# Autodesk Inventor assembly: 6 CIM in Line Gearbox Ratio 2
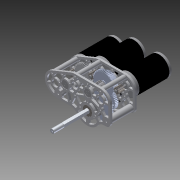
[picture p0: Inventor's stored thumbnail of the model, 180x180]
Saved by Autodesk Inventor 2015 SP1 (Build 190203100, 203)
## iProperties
Created: 2014-11
Part Number: 6 CIM in Line Gearbox Ratio 2
Document SubType Name: Assembly
Designer: Michael
Mass: 4438.01 g
Surface Area: 2514.13 cm^2
Volume: 1336.24 cm^3
Density: 3.32126 g/cm^3
Author: Michael
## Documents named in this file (30)
- C:\Users\User\Documents\6 CIM Gearbox Pack and Go\6 CIM in Line Gearbox Ratio 2.iam
- C:\Users\User\Documents\6 CIM Gearbox Pack and Go\Gearbox Plate Ratio 2.ipt
- C:\Users\User\Documents\6 CIM Gearbox Pack and Go\40T .5 inch.ipt
- C:\Users\User\Documents\6 CIM Gearbox Pack and Go\11t.ipt
- C:\Users\User\Documents\6 CIM Gearbox Pack and Go\50t.ipt
- C:\Users\User\Documents\6 CIM Gearbox Pack and Go\36t.ipt
- C:\Users\User\Documents\6 CIM Gearbox Pack and Go\217-2000 CIM motor.ipt
- C:\Users\User\Documents\6 CIM Gearbox Pack and Go\User Library-16T Gear AndyMark am-0747.ipt
- C:\Users\User\Documents\6 CIM Gearbox Pack and Go\40tDogGear.ipt
- C:\Users\User\Documents\6 CIM Gearbox Pack and Go\60tDogGear.ipt
- C:\Users\User\Documents\6 CIM Gearbox Pack and Go\Gearbox Plate Ratio 2 MIR.ipt
- C:\Users\User\Documents\6 CIM Gearbox Pack and Go\Standoff.ipt
- C:\Users\User\Documents\6 CIM Gearbox Pack and Go\Big Standoff.ipt
- C:\Users\User\Documents\6 CIM Gearbox Pack and Go\217-2428-027 Rev1_97414A630.ipt
- C:\Users\User\Documents\6 CIM Gearbox Pack and Go\217-3423-005 Rev1.ipt
- C:\Users\User\Documents\6 CIM Gearbox Pack and Go\217-3195-200 Rev1.iam
- C:\Users\User\Documents\6 CIM Gearbox Pack and Go\217-3489.ipt
- C:\Users\User\Documents\6 CIM Gearbox Pack and Go\217-3423-006 Rev1.ipt
- C:\Users\User\Documents\6 CIM Gearbox Pack and Go\217-3423-008 Rev1.ipt
- C:\Users\User\Documents\6 CIM Gearbox Pack and Go\217-2778-001 Rev2_NCQ8A075-050M.iam
- C:\Users\User\Documents\6 CIM Gearbox Pack and Go\217-3421-007 Rev1.ipt
- C:\Users\User\Documents\6 CIM Gearbox Pack and Go\217-3423-009 Rev1.ipt
- C:\Users\User\Documents\6 CIM Gearbox Pack and Go\217-3423-003 Rev1.ipt
- C:\Users\User\Documents\6 CIM Gearbox Pack and Go\217-2731.ipt
- C:\Users\User\Documents\6 CIM Gearbox Pack and Go\217-3423-004 Rev1.ipt
- C:\Users\User\Documents\6 CIM Gearbox Pack and Go\217-2743.ipt
- C:\Users\User\Documents\6 CIM Gearbox Pack and Go\217-2734.ipt
- C:\Users\User\Documents\6 CIM Gearbox Pack and Go\217-2733.ipt
- C:\Users\User\Documents\6 CIM Gearbox Pack and Go\217-2640-STEP-20140807.ipt
- C:\Users\User\Documents\6 CIM Gearbox Pack and Go\6cim shaft.ipt
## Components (44 placed, 29 different names)
1. Gearbox Plate Ratio 2:1 — Mate:1, Mate:2, Mate:5, Mate:7, Mate:8, Mate:12, Mate:13, Mate:14, Mate:15, Mate:16, Mate:17, Mate:18, Mate:19, Mate:20, Mate:25, Mate:26, Angle:3, Mate:30, Mate:31, Mate:32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
2. 40T .5 inch:1 — Mate:2, Mate:10, Rotation:5, Rotation:6
3. 11t:1 — Mate:1, Mate:10, Flush:1, Rotation:5
4. 11t:2 — Mate:5, Flush:1, Flush:2, Rotation:6, Rotation:7, Flush:3
5. 50t:1 — Mate:7, Rotation:4, Mate:11, Angle:1, Mate:22, Rotation:7, Mate:24, Angle:2, Flush:3
6. 11t:3 — Mate:8, Rotation:4, Flush:2
7. 36t:1 — Mate:11, Angle:1, Mate:22, Rotation:8, Flush:4
8. 217-2000 CIM motor:1 — Mate:13, Mate:15, Mate:18
9. 217-2000 CIM motor:2 — Mate:14, Mate:16, Mate:19
10. 217-2000 CIM motor:3 — Mate:12, Mate:17, Mate:20
11. User Library-16T Gear AndyMark am-0747:1 — Mate:24, Angle:2, Rotation:9, Mate:81
12. 40tDogGear:1 — Mate:25, Rotation:8, Mate:71, Mate:72
13. 60tDogGear:1 — Mate:26, Angle:3, Rotation:9, Mate:76, Mate:77, Mate:81
14. Gearbox Plate Ratio 2 MIR:1 — Mate:30, Mate:31, Mate:32, Mate:36, Mate:37, Mate:38, Mate:66, Mate:79, Mate:80, Mate:82, Mate:83, Mate:87, Mate:88
15. Standoff:1 — Mate:35, Mate:36
16. Big Standoff:1 — Mate:33, Mate:34
17. Standoff:2 — Mate:41, Mate:42
18. Standoff:3 — Mate:39, Mate:40
19. Big Standoff:2 — Mate:37, Mate:38
20. 217-2428-027 Rev1_97414A630:1 — Mate:52, Mate:53
21. 217-3423-005 Rev1:1 — Mate:44, Mate:45, Mate:46, Mate:47, Mate:48, Mate:56, Mate:57, Mate:58
22. 217-3195-200 Rev1:1 [sub-assembly] — Mate:54, Mate:59, Mate:61
23. 217-3489:1 — Mate:50, Mate:51, Mate:54
24. 217-3423-006 Rev1:1 — Mate:55, Mate:58, Mate:63
25. 217-3423-006 Rev1:2 — Mate:43, Mate:46, Mate:60
26. 217-3423-008 Rev1:1 — Mate:49, Mate:50, Mate:51, Mate:52, Mate:53, Mate:59, Mate:64, Mate:65, Mate:68
27. 217-2778-001 Rev2_NCQ8A075-050M:1 [sub-assembly] — Mate:47, Mate:48, Mate:49, Mate:61
28. 217-3421-007 Rev1:1 — Mate:43, Mate:44, Mate:45
29. 217-3421-007 Rev1:2 — Mate:55, Mate:56, Mate:57, Mate:62
30. 217-3423-009 Rev1:1 — Mate:64, Mate:65
31. 217-3423-003 Rev1:1 — Mate:66, Mate:69, Mate:78
32. 217-2731:1 — Mate:67, Mate:68, Mate:70
33. 217-3423-004 Rev1:1 — Mate:69, Mate:70, Mate:75
34. 217-2743:1 — Mate:71, Mate:72, Mate:75, Flush:4
35. 217-2734:1 — Mate:76, Mate:77, Mate:78, Mate:92, Mate:93
36. 217-2734:2 — Mate:79, Mate:80
37. 217-2733:1 — Mate:82, Mate:87, Mate:95, Flush:6
38. 217-2733:2 — Mate:83, Mate:88, Mate:94, Flush:5
39. 217-2733:3 — Mate:85, Mate:86
40. 217-2733:4 — Mate:84, Mate:89
41. 217-2640-STEP-20140807:1 — Mate:90, Mate:91
42. 217-2640-STEP-20140807:2 — Mate:90, Mate:91, Mate:92, Mate:93
43. 6cim shaft:1 — Mate:94, Flush:5
44. 6cim shaft:3 — Mate:95, Flush:6
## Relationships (99: Mate 84, RelateRotation 6, Flush 6, Angle 3)
- Mate:1: Gearbox Plate Ratio 2:1 ↔ 11t:1
- Mate:2: Gearbox Plate Ratio 2:1 ↔ 40T .5 inch:1
- Mate:5: Gearbox Plate Ratio 2:1 ↔ 11t:2
- Mate:7: Gearbox Plate Ratio 2:1 ↔ 50t:1
- Mate:8: Gearbox Plate Ratio 2:1 ↔ 11t:3
- Mate:10: 40T .5 inch:1 ↔ 11t:1
- Rotation:4 [RelateRotation]: 50t:1 ↔ 11t:3
- Mate:11: 50t:1 ↔ 36t:1
- Angle:1: 50t:1 ↔ 36t:1
- Mate:12: Gearbox Plate Ratio 2:1 ↔ 217-2000 CIM motor:3
- Mate:13: Gearbox Plate Ratio 2:1 ↔ 217-2000 CIM motor:1
- Mate:14: Gearbox Plate Ratio 2:1 ↔ 217-2000 CIM motor:2
- Mate:15: Gearbox Plate Ratio 2:1 ↔ 217-2000 CIM motor:1
- Mate:16: Gearbox Plate Ratio 2:1 ↔ 217-2000 CIM motor:2
- Mate:17: Gearbox Plate Ratio 2:1 ↔ 217-2000 CIM motor:3
- Mate:18: Gearbox Plate Ratio 2:1 ↔ 217-2000 CIM motor:1
- Mate:19: Gearbox Plate Ratio 2:1 ↔ 217-2000 CIM motor:2
- Mate:20: Gearbox Plate Ratio 2:1 ↔ 217-2000 CIM motor:3
- Flush:1: 11t:1 ↔ 11t:2
- Flush:2: 11t:2 ↔ 11t:3
- Mate:22: 50t:1 ↔ 36t:1
- Rotation:5 [RelateRotation]: 40T .5 inch:1 ↔ 11t:1
- Rotation:6 [RelateRotation]: 40T .5 inch:1 ↔ 11t:2
- Rotation:7 [RelateRotation]: 11t:2 ↔ 50t:1
- Mate:24: 50t:1 ↔ User Library-16T Gear AndyMark am-0747:1
- Angle:2: 50t:1 ↔ User Library-16T Gear AndyMark am-0747:1
- Mate:25: Gearbox Plate Ratio 2:1 ↔ 40tDogGear:1
- Mate:26: Gearbox Plate Ratio 2:1 ↔ 60tDogGear:1
- Angle:3: Gearbox Plate Ratio 2:1 ↔ 60tDogGear:1
- Rotation:8 [RelateRotation]: 36t:1 ↔ 40tDogGear:1
- Rotation:9 [RelateRotation]: User Library-16T Gear AndyMark am-0747:1 ↔ 60tDogGear:1
- Mate:30: Gearbox Plate Ratio 2:1 ↔ Gearbox Plate Ratio 2 MIR:1
- Mate:31: Gearbox Plate Ratio 2:1 ↔ Gearbox Plate Ratio 2 MIR:1
- Mate:32: Gearbox Plate Ratio 2:1 ↔ Gearbox Plate Ratio 2 MIR:1
- Mate:33: Gearbox Plate Ratio 2:1 ↔ Big Standoff:1
- Mate:34: Gearbox Plate Ratio 2:1 ↔ Big Standoff:1
- Mate:35: Gearbox Plate Ratio 2:1 ↔ Standoff:1
- Mate:36: Gearbox Plate Ratio 2 MIR:1 ↔ Standoff:1
- Mate:37: Gearbox Plate Ratio 2 MIR:1 ↔ Big Standoff:2
- Mate:38: Gearbox Plate Ratio 2 MIR:1 ↔ Big Standoff:2
- Mate:39: Gearbox Plate Ratio 2:1 ↔ Standoff:3
- Mate:40: Gearbox Plate Ratio 2:1 ↔ Standoff:3
- Mate:41: Gearbox Plate Ratio 2:1 ↔ Standoff:2
- Mate:42: Gearbox Plate Ratio 2:1 ↔ Standoff:2
- Mate:43: 217-3423-006 Rev1:2 ↔ 217-3421-007 Rev1:1
- Mate:44: 217-3423-005 Rev1:1 ↔ 217-3421-007 Rev1:1
- Mate:45: 217-3423-005 Rev1:1 ↔ 217-3421-007 Rev1:1
- Mate:46: 217-3423-005 Rev1:1 ↔ 217-3423-006 Rev1:2
- Mate:47: 217-3423-005 Rev1:1 ↔ 217-2778-001 Rev2_NCQ8A075-050M:1
- Mate:48: 217-3423-005 Rev1:1 ↔ 217-2778-001 Rev2_NCQ8A075-050M:1
- Mate:49: 217-3423-008 Rev1:1 ↔ 217-2778-001 Rev2_NCQ8A075-050M:1
- Mate:50: 217-3489:1 ↔ 217-3423-008 Rev1:1
- Mate:51: 217-3489:1 ↔ 217-3423-008 Rev1:1
- Mate:52: 217-2428-027 Rev1_97414A630:1 ↔ 217-3423-008 Rev1:1
- Mate:53: 217-2428-027 Rev1_97414A630:1 ↔ 217-3423-008 Rev1:1
- Mate:54: 217-3195-200 Rev1:1 ↔ 217-3489:1
- Mate:55: 217-3423-006 Rev1:1 ↔ 217-3421-007 Rev1:2
- Mate:56: 217-3423-005 Rev1:1 ↔ 217-3421-007 Rev1:2
- Mate:57: 217-3423-005 Rev1:1 ↔ 217-3421-007 Rev1:2
- Mate:58: 217-3423-005 Rev1:1 ↔ 217-3423-006 Rev1:1
- Mate:59: 217-3195-200 Rev1:1 ↔ 217-3423-008 Rev1:1
- Mate:60: Gearbox Plate Ratio 2:1 ↔ 217-3423-006 Rev1:2
- Mate:61: 217-3195-200 Rev1:1 ↔ 217-2778-001 Rev2_NCQ8A075-050M:1
- Mate:62: Gearbox Plate Ratio 2:1 ↔ 217-3421-007 Rev1:2
- Mate:63: Gearbox Plate Ratio 2:1 ↔ 217-3423-006 Rev1:1
- Mate:64: 217-3423-008 Rev1:1 ↔ 217-3423-009 Rev1:1
- Mate:65: 217-3423-008 Rev1:1 ↔ 217-3423-009 Rev1:1
- Mate:66: Gearbox Plate Ratio 2 MIR:1 ↔ 217-3423-003 Rev1:1
- Mate:67: Gearbox Plate Ratio 2:1 ↔ 217-2731:1
- Mate:68: 217-3423-008 Rev1:1 ↔ 217-2731:1
- Mate:69: 217-3423-003 Rev1:1 ↔ 217-3423-004 Rev1:1
- Mate:70: 217-2731:1 ↔ 217-3423-004 Rev1:1
- Mate:71: 40tDogGear:1 ↔ 217-2743:1
- Mate:72: 40tDogGear:1 ↔ 217-2743:1
- Mate:75: 217-3423-004 Rev1:1 ↔ 217-2743:1
- Mate:76: 60tDogGear:1 ↔ 217-2734:1
- Mate:77: 60tDogGear:1 ↔ 217-2734:1
- Mate:78: 217-3423-003 Rev1:1 ↔ 217-2734:1
- Mate:79: Gearbox Plate Ratio 2 MIR:1 ↔ 217-2734:2
- Mate:80: Gearbox Plate Ratio 2 MIR:1 ↔ 217-2734:2
- Mate:81: User Library-16T Gear AndyMark am-0747:1 ↔ 60tDogGear:1
- Mate:82: Gearbox Plate Ratio 2 MIR:1 ↔ 217-2733:1
- Mate:83: Gearbox Plate Ratio 2 MIR:1 ↔ 217-2733:2
- Mate:84: Gearbox Plate Ratio 2:1 ↔ 217-2733:4
- Mate:85: Gearbox Plate Ratio 2:1 ↔ 217-2733:3
- Mate:86: Gearbox Plate Ratio 2:1 ↔ 217-2733:3
- Mate:87: Gearbox Plate Ratio 2 MIR:1 ↔ 217-2733:1
- Mate:88: Gearbox Plate Ratio 2 MIR:1 ↔ 217-2733:2
- Mate:89: Gearbox Plate Ratio 2:1 ↔ 217-2733:4
- Mate:90: 217-2640-STEP-20140807:1 ↔ 217-2640-STEP-20140807:2
- Mate:91: 217-2640-STEP-20140807:1 ↔ 217-2640-STEP-20140807:2
- Mate:92: 217-2734:1 ↔ 217-2640-STEP-20140807:2
- Mate:93: 217-2734:1 ↔ 217-2640-STEP-20140807:2
- Flush:3: 11t:2 ↔ 50t:1
- Flush:4: 36t:1 ↔ 217-2743:1
- Mate:94: 217-2733:2 ↔ 6cim shaft:1
- Flush:5: 217-2733:2 ↔ 6cim shaft:1
- Mate:95: 217-2733:1 ↔ 6cim shaft:3
- Flush:6: 217-2733:1 ↔ 6cim shaft:3
